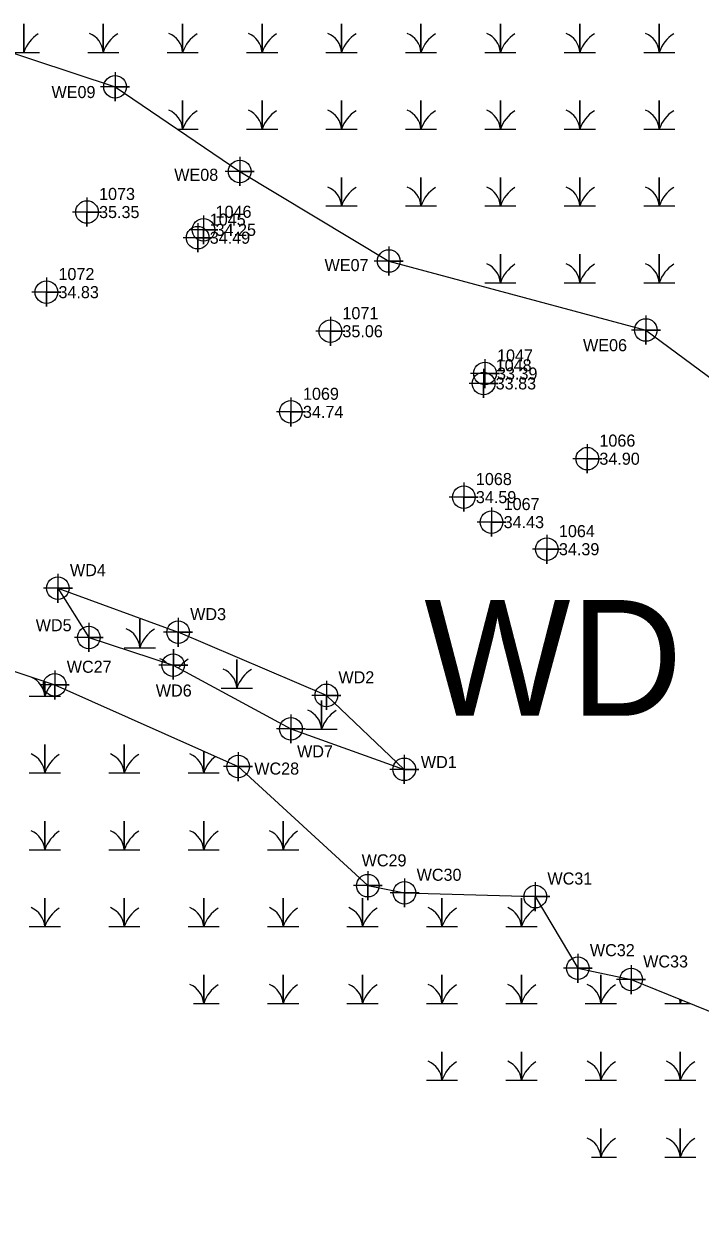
# Model space of a CAD drawing. Extents: x 2138832 to 2141061, y 149156 to 150675.
# Drawn here: x 2140647 to 2140787, y 149199.9 to 149446.4 of the extents above; entities that cross this region are included whole.
import ezdxf

# ---------------------------------------------------------------- set-up
doc = ezdxf.new("R2010")
doc.units = 0
for name, color, linetype in [('Default', 7, 'Continuous'), ('Exist Environmental Wetland Boundary', 7, 'Continuous'), ('Exist Environmental Wetland Boundary Cogo Number', 7, 'Continuous'), ('Exist Environmental Wetland Boundary Cogo Point CELL', 7, 'Continuous'), ('Exist Roads EOP Cogo Elevation', 7, 'Continuous'), ('Exist Roads EOP Cogo Number', 7, 'Continuous'), ('Exist Roads EOP Cogo Point CELL', 7, 'Continuous'), ('Exist Utilities Telephone UG FO SUE LOS C Cogo Elevation', 7, 'Continuous'), ('Exist Utilities Telephone UG FO SUE LOS C Cogo Number', 7, 'Continuous'), ('Exist Utilities Telephone UG FO SUE LOS C Cogo Point CELL', 7, 'Continuous')]:
    doc.layers.add(name, color=color, linetype=linetype)

msp = doc.modelspace()

# ---------------------------------------------------------------- linework, layer by layer
at = {"layer": 'Exist Environmental Wetland Boundary'}
for points in [[(2140626.92, 149434.6), (2140640.09, 149441.77), (2140665.85, 149433.31), (2140691.67, 149415.77), (2140722.53, 149397.21), (2140775.79, 149382.91), (2140815.44, 149353.55), (2140873.49, 149322.65), (2140932.75, 149291.76), (2140974.9, 149268.42), (2141022.6, 149236.76)], [(2140585.59, 149347.19), (2140617.17, 149321.45), (2140653.35, 149309.39)], [(2140654.01, 149329.41), (2140660.42, 149319.22), (2140677.9, 149313.49), (2140702.28, 149300.28)], [(2140654.01, 149329.41), (2140678.91, 149320.3)], [(2140725.75, 149291.89), (2140709.61, 149307.21), (2140678.91, 149320.3)], [(2140653.35, 149309.39), (2140691.33, 149292.47), (2140718.2, 149267.79)], [(2140702.28, 149300.28), (2140725.75, 149291.89)], [(2140718.2, 149267.79), (2140725.81, 149266.3), (2140752.89, 149265.52), (2140761.69, 149250.68), (2140772.72, 149248.34), (2140790.93, 149240.98), (2140838.41, 149220.19), (2140876.86, 149199.92)]]:
    msp.add_lwpolyline(points, dxfattribs=at)
at = {"layer": 'Exist Environmental Wetland Boundary Cogo Point CELL'}
for points in [[(2140644.13, 149440.44), (2140646.95, 149440.44), (2140646.95, 149446.36), (2140646.95, 149440.44), (2140650.18, 149440.44)], [(2140660.18, 149440.44), (2140663.4, 149440.44), (2140663.4, 149446.36), (2140663.4, 149440.44), (2140666.63, 149440.44)], [(2140676.63, 149440.44), (2140679.85, 149440.44), (2140679.85, 149446.36), (2140679.85, 149440.44), (2140683.08, 149440.44)], [(2140693.08, 149440.44), (2140696.3, 149440.44), (2140696.3, 149446.36), (2140696.3, 149440.44), (2140699.53, 149440.44)], [(2140709.53, 149440.44), (2140712.76, 149440.44), (2140712.76, 149446.36), (2140712.76, 149440.44), (2140715.98, 149440.44)], [(2140725.98, 149440.44), (2140729.21, 149440.44), (2140729.21, 149446.36), (2140729.21, 149440.44), (2140732.43, 149440.44)], [(2140742.43, 149440.44), (2140745.66, 149440.44), (2140745.66, 149446.36), (2140745.66, 149440.44), (2140748.88, 149440.44)], [(2140758.88, 149440.44), (2140762.11, 149440.44), (2140762.11, 149446.36), (2140762.11, 149440.44), (2140765.34, 149440.44)], [(2140775.34, 149440.44), (2140778.56, 149440.44), (2140778.56, 149446.36), (2140778.56, 149440.44), (2140781.79, 149440.44)], [(2140665.85, 149436.31), (2140665.85, 149430.31), (2140665.85, 149433.31), (2140668.85, 149433.31), (2140662.85, 149433.31)], [(2140678.79, 149424.52), (2140679.85, 149424.52), (2140679.85, 149430.44), (2140679.85, 149424.52), (2140683.08, 149424.52)], [(2140693.08, 149424.52), (2140696.3, 149424.52), (2140696.3, 149430.44), (2140696.3, 149424.52), (2140699.53, 149424.52)], [(2140709.53, 149424.52), (2140712.76, 149424.52), (2140712.76, 149430.44), (2140712.76, 149424.52), (2140715.98, 149424.52)], [(2140725.98, 149424.52), (2140729.21, 149424.52), (2140729.21, 149430.44), (2140729.21, 149424.52), (2140732.43, 149424.52)], [(2140742.43, 149424.52), (2140745.66, 149424.52), (2140745.66, 149430.44), (2140745.66, 149424.52), (2140748.88, 149424.52)], [(2140758.88, 149424.52), (2140762.11, 149424.52), (2140762.11, 149430.44), (2140762.11, 149424.52), (2140765.34, 149424.52)], [(2140775.34, 149424.52), (2140778.56, 149424.52), (2140778.56, 149430.44), (2140778.56, 149424.52), (2140781.79, 149424.52)], [(2140691.67, 149418.77), (2140691.67, 149412.77), (2140691.67, 149415.77), (2140694.67, 149415.77), (2140688.67, 149415.77)], [(2140709.53, 149408.61), (2140712.76, 149408.61), (2140712.76, 149414.52), (2140712.76, 149408.61), (2140715.98, 149408.61)], [(2140725.98, 149408.61), (2140729.21, 149408.61), (2140729.21, 149414.52), (2140729.21, 149408.61), (2140732.43, 149408.61)], [(2140742.43, 149408.61), (2140745.66, 149408.61), (2140745.66, 149414.52), (2140745.66, 149408.61), (2140748.88, 149408.61)], [(2140758.88, 149408.61), (2140762.11, 149408.61), (2140762.11, 149414.52), (2140762.11, 149408.61), (2140765.34, 149408.61)], [(2140775.34, 149408.61), (2140778.56, 149408.61), (2140778.56, 149414.52), (2140778.56, 149408.61), (2140781.79, 149408.61)], [(2140722.53, 149400.21), (2140722.53, 149394.21), (2140722.53, 149397.21), (2140725.53, 149397.21), (2140719.53, 149397.21)], [(2140742.43, 149392.69), (2140745.66, 149392.69), (2140745.66, 149398.61), (2140745.66, 149392.69), (2140748.88, 149392.69)], [(2140758.88, 149392.69), (2140762.11, 149392.69), (2140762.11, 149398.61), (2140762.11, 149392.69), (2140765.34, 149392.69)], [(2140775.34, 149392.69), (2140778.56, 149392.69), (2140778.56, 149398.61), (2140778.56, 149392.69), (2140781.79, 149392.69)], [(2140775.79, 149385.91), (2140775.79, 149379.91), (2140775.79, 149382.91), (2140778.79, 149382.91), (2140772.79, 149382.91)], [(2140654.01, 149332.41), (2140654.01, 149326.41), (2140654.01, 149329.41), (2140657.01, 149329.41), (2140651.01, 149329.41)], [(2140667.75, 149317.08), (2140670.98, 149317.08), (2140670.98, 149323), (2140670.98, 149317.08), (2140674.2, 149317.08)], [(2140678.91, 149323.3), (2140678.91, 149317.3), (2140678.91, 149320.3), (2140681.91, 149320.3), (2140675.91, 149320.3)], [(2140660.42, 149322.22), (2140660.42, 149316.22), (2140660.42, 149319.22), (2140663.42, 149319.22), (2140657.42, 149319.22)], [(2140677.9, 149316.49), (2140677.9, 149310.49), (2140677.9, 149313.49), (2140680.9, 149313.49), (2140674.9, 149313.49)], [(2140677.98, 149313.45), (2140677.98, 149316.8), (2140677.98, 149313.45)], [(2140687.86, 149308.73), (2140691.09, 149308.73), (2140691.09, 149314.64), (2140691.09, 149308.73), (2140694.32, 149308.73)], [(2140653.35, 149312.39), (2140653.35, 149306.39), (2140653.35, 149309.39), (2140656.35, 149309.39), (2140650.35, 149309.39)], [(2140648.08, 149307.06), (2140651.3, 149307.06), (2140651.3, 149310.07)], [(2140651.3, 149310.07), (2140651.3, 149307.06), (2140654.53, 149307.06)], [(2140709.61, 149310.21), (2140709.61, 149304.21), (2140709.61, 149307.21), (2140712.61, 149307.21), (2140706.61, 149307.21)], [(2140705.4, 149300.22), (2140708.63, 149300.22), (2140708.63, 149306.13), (2140708.63, 149300.22), (2140711.86, 149300.22)], [(2140702.28, 149303.28), (2140702.28, 149297.28), (2140702.28, 149300.28), (2140705.28, 149300.28), (2140699.28, 149300.28)], [(2140648.08, 149291.14), (2140651.3, 149291.14), (2140651.3, 149297.06), (2140651.3, 149291.14), (2140654.53, 149291.14)], [(2140664.53, 149291.14), (2140667.75, 149291.14), (2140667.75, 149297.06), (2140667.75, 149291.14), (2140670.98, 149291.14)], [(2140680.98, 149291.14), (2140684.21, 149291.14), (2140684.21, 149295.64)], [(2140684.21, 149295.64), (2140684.21, 149291.14), (2140687.43, 149291.14)], [(2140691.33, 149295.47), (2140691.33, 149289.47), (2140691.33, 149292.47), (2140694.33, 149292.47), (2140688.33, 149292.47)], [(2140725.75, 149294.89), (2140725.75, 149288.89), (2140725.75, 149291.89), (2140728.75, 149291.89), (2140722.75, 149291.89)], [(2140648.08, 149275.22), (2140651.3, 149275.22), (2140651.3, 149281.14), (2140651.3, 149275.22), (2140654.53, 149275.22)], [(2140664.53, 149275.22), (2140667.75, 149275.22), (2140667.75, 149281.14), (2140667.75, 149275.22), (2140670.98, 149275.22)], [(2140680.98, 149275.22), (2140684.21, 149275.22), (2140684.21, 149281.14), (2140684.21, 149275.22), (2140687.43, 149275.22)], [(2140697.43, 149275.22), (2140700.66, 149275.22), (2140700.66, 149281.14), (2140700.66, 149275.22), (2140703.88, 149275.22)], [(2140718.2, 149270.79), (2140718.2, 149264.79), (2140718.2, 149267.79), (2140721.2, 149267.79), (2140715.2, 149267.79)], [(2140725.81, 149269.3), (2140725.81, 149263.3), (2140725.81, 149266.3), (2140728.81, 149266.3), (2140722.81, 149266.3)], [(2140752.89, 149268.52), (2140752.89, 149262.52), (2140752.89, 149265.52), (2140755.89, 149265.52), (2140749.89, 149265.52)], [(2140648.08, 149259.31), (2140651.3, 149259.31), (2140651.3, 149265.22), (2140651.3, 149259.31), (2140654.53, 149259.31)], [(2140664.53, 149259.31), (2140667.75, 149259.31), (2140667.75, 149265.22), (2140667.75, 149259.31), (2140670.98, 149259.31)], [(2140680.98, 149259.31), (2140684.21, 149259.31), (2140684.21, 149265.22), (2140684.21, 149259.31), (2140687.43, 149259.31)], [(2140697.43, 149259.31), (2140700.66, 149259.31), (2140700.66, 149265.22), (2140700.66, 149259.31), (2140703.88, 149259.31)], [(2140713.88, 149259.31), (2140717.11, 149259.31), (2140717.11, 149265.22), (2140717.11, 149259.31), (2140720.33, 149259.31)], [(2140730.33, 149259.31), (2140733.56, 149259.31), (2140733.56, 149265.22), (2140733.56, 149259.31), (2140736.79, 149259.31)], [(2140746.79, 149259.31), (2140750.01, 149259.31), (2140750.01, 149265.22), (2140750.01, 149259.31), (2140753.24, 149259.31)], [(2140761.69, 149253.68), (2140761.69, 149247.68), (2140761.69, 149250.68), (2140764.69, 149250.68), (2140758.69, 149250.68)], [(2140772.72, 149251.34), (2140772.72, 149245.34), (2140772.72, 149248.34), (2140775.72, 149248.34), (2140769.72, 149248.34)], [(2140682.1, 149243.39), (2140684.21, 149243.39), (2140684.21, 149249.31), (2140684.21, 149243.39), (2140687.43, 149243.39)], [(2140697.43, 149243.39), (2140700.66, 149243.39), (2140700.66, 149249.31), (2140700.66, 149243.39), (2140703.88, 149243.39)], [(2140713.88, 149243.39), (2140717.11, 149243.39), (2140717.11, 149249.31), (2140717.11, 149243.39), (2140720.33, 149243.39)], [(2140730.33, 149243.39), (2140733.56, 149243.39), (2140733.56, 149249.31), (2140733.56, 149243.39), (2140736.79, 149243.39)], [(2140746.79, 149243.39), (2140750.01, 149243.39), (2140750.01, 149249.31), (2140750.01, 149243.39), (2140753.24, 149243.39)], [(2140763.24, 149243.39), (2140766.46, 149243.39), (2140766.46, 149249.31), (2140766.46, 149243.39), (2140769.69, 149243.39)], [(2140779.69, 149243.39), (2140782.91, 149243.39), (2140782.91, 149244.22)], [(2140782.91, 149244.22), (2140782.91, 149243.39), (2140784.98, 149243.39)], [(2140730.33, 149227.47), (2140733.56, 149227.47), (2140733.56, 149233.39), (2140733.56, 149227.47), (2140736.79, 149227.47)], [(2140746.79, 149227.47), (2140750.01, 149227.47), (2140750.01, 149233.39), (2140750.01, 149227.47), (2140753.24, 149227.47)], [(2140763.24, 149227.47), (2140766.46, 149227.47), (2140766.46, 149233.39), (2140766.46, 149227.47), (2140769.69, 149227.47)], [(2140779.69, 149227.47), (2140782.91, 149227.47), (2140782.91, 149233.39), (2140782.91, 149227.47), (2140786.14, 149227.47)], [(2140764.54, 149211.55), (2140766.46, 149211.55), (2140766.46, 149217.47), (2140766.46, 149211.55), (2140769.69, 149211.55)], [(2140779.69, 149211.55), (2140782.91, 149211.55), (2140782.91, 149217.47), (2140782.91, 149211.55), (2140786.14, 149211.55)]]:
    msp.add_lwpolyline(points, dxfattribs=at)
for centre in [(2140665.85, 149433.31), (2140691.67, 149415.77), (2140722.53, 149397.21), (2140775.79, 149382.91), (2140654.01, 149329.41), (2140678.91, 149320.3), (2140660.42, 149319.22), (2140677.9, 149313.49), (2140653.35, 149309.39), (2140709.61, 149307.21), (2140702.28, 149300.28), (2140691.33, 149292.47), (2140725.75, 149291.89), (2140718.2, 149267.79), (2140725.81, 149266.3), (2140752.89, 149265.52), (2140761.69, 149250.68), (2140772.72, 149248.34)]:
    msp.add_circle(centre, 2.34, dxfattribs=at)
for centre, radius, start, end in [((2140653.79, 149438.17), 7.21, 122.1274, 161.6222), ((2140658.8, 149440.11), 4.61, 4.1403, 67.535), ((2140670.24, 149438.17), 7.21, 122.1274, 161.6222), ((2140675.25, 149440.11), 4.61, 4.1403, 67.535), ((2140686.69, 149438.17), 7.21, 122.1274, 161.6222), ((2140691.7, 149440.11), 4.61, 4.1403, 67.535), ((2140703.15, 149438.17), 7.21, 122.1274, 161.6222), ((2140708.16, 149440.11), 4.61, 4.1403, 67.535), ((2140719.6, 149438.17), 7.21, 122.1274, 161.6222), ((2140724.61, 149440.11), 4.61, 4.1403, 67.535), ((2140736.05, 149438.17), 7.21, 122.1274, 161.6222), ((2140741.06, 149440.11), 4.61, 4.1403, 67.535), ((2140752.5, 149438.17), 7.21, 122.1274, 161.6222), ((2140757.51, 149440.11), 4.61, 4.1403, 67.535), ((2140768.95, 149438.17), 7.21, 122.1274, 161.6222), ((2140773.96, 149440.11), 4.61, 4.1403, 67.535), ((2140785.4, 149438.17), 7.21, 122.1274, 161.6222), ((2140675.25, 149424.19), 4.61, 4.1403, 67.535), ((2140686.69, 149422.25), 7.21, 122.1274, 161.6222), ((2140691.7, 149424.19), 4.61, 4.1403, 67.535), ((2140703.15, 149422.25), 7.21, 122.1274, 161.6222), ((2140708.16, 149424.19), 4.61, 4.1403, 67.535), ((2140719.6, 149422.25), 7.21, 122.1274, 161.6222), ((2140724.61, 149424.19), 4.61, 4.1403, 67.535), ((2140736.05, 149422.25), 7.21, 122.1274, 161.6222), ((2140741.06, 149424.19), 4.61, 4.1403, 67.535), ((2140752.5, 149422.25), 7.21, 122.1274, 161.6222), ((2140757.51, 149424.19), 4.61, 4.1403, 67.535), ((2140768.95, 149422.25), 7.21, 122.1274, 161.6222), ((2140773.96, 149424.19), 4.61, 4.1403, 67.535), ((2140785.4, 149422.25), 7.21, 122.1274, 161.6222), ((2140708.16, 149408.27), 4.61, 4.1403, 67.535), ((2140719.6, 149406.33), 7.21, 122.1274, 161.6222), ((2140724.61, 149408.27), 4.61, 4.1403, 67.535), ((2140736.05, 149406.33), 7.21, 122.1274, 161.6222), ((2140741.06, 149408.27), 4.61, 4.1403, 67.535), ((2140752.5, 149406.33), 7.21, 122.1274, 161.6222), ((2140757.51, 149408.27), 4.61, 4.1403, 67.535), ((2140768.95, 149406.33), 7.21, 122.1274, 161.6222), ((2140773.96, 149408.27), 4.61, 4.1403, 67.535), ((2140785.4, 149406.33), 7.21, 122.1274, 161.6222), ((2140741.06, 149392.36), 4.61, 4.1403, 67.535), ((2140757.51, 149392.36), 4.61, 4.1403, 67.535), ((2140773.96, 149392.36), 4.61, 4.1403, 67.535), ((2140752.5, 149390.42), 7.21, 122.1274, 161.6222), ((2140768.95, 149390.42), 7.21, 122.1274, 161.6222), ((2140785.4, 149390.42), 7.21, 122.1274, 161.6222), ((2140666.38, 149316.75), 4.61, 4.1403, 67.535), ((2140677.82, 149314.81), 7.21, 122.1274, 161.6222), ((2140673.38, 149310.55), 4.61, 47.5643, 67.535), ((2140684.82, 149308.61), 7.21, 122.1274, 143.5992), ((2140646.7, 149306.73), 4.61, 4.1403, 67.535), ((2140686.49, 149308.39), 4.61, 4.1403, 67.535), ((2140697.93, 149306.45), 7.21, 122.1274, 161.6222), ((2140658.14, 149304.79), 7.21, 138.3045, 161.6222), ((2140704.03, 149299.88), 4.61, 4.1403, 67.535), ((2140715.47, 149297.94), 7.21, 122.1274, 161.6222), ((2140646.7, 149290.81), 4.61, 4.1403, 67.535), ((2140658.14, 149288.87), 7.21, 122.1274, 161.6222), ((2140663.15, 149290.81), 4.61, 4.1403, 67.535), ((2140674.6, 149288.87), 7.21, 122.1274, 161.6222), ((2140679.61, 149290.81), 4.61, 4.1403, 67.535), ((2140691.05, 149288.87), 7.21, 127.7972, 161.6222), ((2140646.7, 149274.89), 4.61, 4.1403, 67.535), ((2140658.14, 149272.95), 7.21, 122.1274, 161.6222), ((2140663.15, 149274.89), 4.61, 4.1403, 67.535), ((2140674.6, 149272.95), 7.21, 122.1274, 161.6222), ((2140679.61, 149274.89), 4.61, 4.1403, 67.535), ((2140691.05, 149272.95), 7.21, 122.1274, 161.6222), ((2140696.06, 149274.89), 4.61, 4.1403, 67.535), ((2140707.5, 149272.95), 7.21, 122.1274, 161.6222), ((2140646.7, 149258.97), 4.61, 4.1403, 67.535), ((2140658.14, 149257.03), 7.21, 122.1274, 161.6222), ((2140663.15, 149258.97), 4.61, 4.1403, 67.535), ((2140674.6, 149257.03), 7.21, 122.1274, 161.6222), ((2140679.61, 149258.97), 4.61, 4.1403, 67.535), ((2140691.05, 149257.03), 7.21, 122.1274, 161.6222), ((2140696.06, 149258.97), 4.61, 4.1403, 67.535), ((2140707.5, 149257.03), 7.21, 122.1274, 161.6222), ((2140712.51, 149258.97), 4.61, 4.1403, 67.535), ((2140723.95, 149257.03), 7.21, 122.1274, 161.6222), ((2140728.96, 149258.97), 4.61, 4.1403, 67.535), ((2140740.4, 149257.03), 7.21, 122.1274, 161.6222), ((2140745.41, 149258.97), 4.61, 4.1403, 67.535), ((2140756.85, 149257.03), 7.21, 122.1274, 161.6222), ((2140679.61, 149243.05), 4.61, 4.1403, 67.535), ((2140691.05, 149241.12), 7.21, 122.1274, 161.6222), ((2140696.06, 149243.05), 4.61, 4.1403, 67.535), ((2140707.5, 149241.12), 7.21, 122.1274, 161.6222), ((2140712.51, 149243.05), 4.61, 4.1403, 67.535), ((2140723.95, 149241.12), 7.21, 122.1274, 161.6222), ((2140728.96, 149243.05), 4.61, 4.1403, 67.535), ((2140740.4, 149241.12), 7.21, 122.1274, 161.6222), ((2140745.41, 149243.05), 4.61, 4.1403, 67.535), ((2140756.85, 149241.12), 7.21, 122.1274, 161.6222), ((2140761.86, 149243.05), 4.61, 4.1403, 67.535), ((2140773.3, 149241.12), 7.21, 122.1274, 161.6222), ((2140778.31, 149243.05), 4.61, 4.1403, 15.4513), ((2140789.75, 149241.12), 7.21, 155.4777, 161.6222), ((2140728.96, 149227.14), 4.61, 4.1403, 67.535), ((2140740.4, 149225.2), 7.21, 122.1274, 161.6222), ((2140745.41, 149227.14), 4.61, 4.1403, 67.535), ((2140756.85, 149225.2), 7.21, 122.1274, 161.6222), ((2140761.86, 149227.14), 4.61, 4.1403, 67.535), ((2140773.3, 149225.2), 7.21, 122.1274, 161.6222), ((2140778.31, 149227.14), 4.61, 4.1403, 67.535), ((2140789.75, 149225.2), 7.21, 122.1274, 161.6222), ((2140761.86, 149211.22), 4.61, 4.1403, 67.535), ((2140773.3, 149209.28), 7.21, 122.1274, 161.6222), ((2140778.31, 149211.22), 4.61, 4.1403, 67.535), ((2140789.75, 149209.28), 7.21, 122.1274, 161.6222)]:
    msp.add_arc(centre, radius, start, end, dxfattribs=at)
at = {"layer": 'Exist Roads EOP Cogo Point CELL'}
for points in [[(2140660.04, 149410.36), (2140660.04, 149404.36), (2140660.04, 149407.36), (2140663.04, 149407.36), (2140657.04, 149407.36)], [(2140651.63, 149393.76), (2140651.63, 149387.76), (2140651.63, 149390.76), (2140654.63, 149390.76), (2140648.63, 149390.76)], [(2140710.44, 149385.66), (2140710.44, 149379.66), (2140710.44, 149382.66), (2140713.44, 149382.66), (2140707.44, 149382.66)], [(2140702.27, 149368.95), (2140702.27, 149362.95), (2140702.27, 149365.95), (2140705.27, 149365.95), (2140699.27, 149365.95)], [(2140763.66, 149359.25), (2140763.66, 149353.25), (2140763.66, 149356.25), (2140766.66, 149356.25), (2140760.66, 149356.25)], [(2140738.08, 149351.29), (2140738.08, 149345.29), (2140738.08, 149348.29), (2140741.08, 149348.29), (2140735.08, 149348.29)], [(2140743.83, 149346.11), (2140743.83, 149340.11), (2140743.83, 149343.11), (2140746.83, 149343.11), (2140740.83, 149343.11)], [(2140755.28, 149340.5), (2140755.28, 149334.5), (2140755.28, 149337.5), (2140758.28, 149337.5), (2140752.28, 149337.5)]]:
    msp.add_lwpolyline(points, dxfattribs=at)
for centre in [(2140660.04, 149407.36), (2140651.63, 149390.76), (2140710.44, 149382.66), (2140702.27, 149365.95), (2140763.66, 149356.25), (2140738.08, 149348.29), (2140743.83, 149343.11), (2140755.28, 149337.5)]:
    msp.add_circle(centre, 2.34, dxfattribs=at)
at = {"layer": 'Exist Utilities Telephone UG FO SUE LOS C Cogo Point CELL'}
for points in [[(2140684.17, 149406.67), (2140684.17, 149400.67), (2140684.17, 149403.67), (2140687.17, 149403.67), (2140681.17, 149403.67)], [(2140682.96, 149405.04), (2140682.96, 149399.04), (2140682.96, 149402.04), (2140685.96, 149402.04), (2140679.96, 149402.04)], [(2140742.46, 149376.89), (2140742.46, 149370.89), (2140742.46, 149373.89), (2140745.46, 149373.89), (2140739.46, 149373.89)], [(2140742.18, 149374.85), (2140742.18, 149368.85), (2140742.18, 149371.85), (2140745.18, 149371.85), (2140739.18, 149371.85)]]:
    msp.add_lwpolyline(points, dxfattribs=at)
for centre in [(2140682.96, 149402.04), (2140684.17, 149403.67), (2140742.46, 149373.89), (2140742.18, 149371.85)]:
    msp.add_circle(centre, 2.34, dxfattribs=at)

# ---------------------------------------------------------------- texts
at = {"layer": 'Default'}
msp.add_text('WD', height=24, dxfattribs=at).set_placement((2140729.88, 149302.98))
at = {"layer": 'Exist Environmental Wetland Boundary Cogo Number'}
for s, p in [('WE09', (2140652.69, 149430.97)), ('WE08', (2140678.11, 149413.82)), ('WE07', (2140709.24, 149395.12)), ('WE06', (2140762.77, 149378.52)), ('WD4', (2140656.51, 149331.91)), ('WD3', (2140681.41, 149322.8)), ('WD5', (2140649.42, 149320.5)), ('WC27', (2140655.85, 149311.89)), ('WD2', (2140712.11, 149309.71)), ('WD6', (2140674.29, 149306.97)), ('WD7', (2140703.55, 149294.36)), ('WC28', (2140694.68, 149290.8)), ('WD1', (2140729.18, 149292.15)), ('WC29', (2140716.92, 149271.78)), ('WC30', (2140728.31, 149268.8)), ('WC31', (2140755.39, 149268.02)), ('WC32', (2140764.19, 149253.18)), ('WC33', (2140775.22, 149250.84))]:
    msp.add_text(s, height=2.5, dxfattribs=at).set_placement(p)
at = {"layer": 'Exist Roads EOP Cogo Elevation'}
for s, p in [('35.35', (2140662.54, 149406.11)), ('34.83', (2140654.13, 149389.51)), ('35.06', (2140712.94, 149381.41)), ('34.74', (2140704.77, 149364.7)), ('34.90', (2140766.16, 149355)), ('34.59', (2140740.58, 149347.04)), ('34.43', (2140746.33, 149341.86)), ('34.39', (2140757.78, 149336.25))]:
    msp.add_text(s, height=2.5, dxfattribs=at).set_placement(p)
at = {"layer": 'Exist Roads EOP Cogo Number'}
for s, p in [('1073', (2140662.54, 149409.86)), ('1072', (2140654.13, 149393.26)), ('1071', (2140712.94, 149385.16)), ('1069', (2140704.77, 149368.45)), ('1066', (2140766.16, 149358.75)), ('1068', (2140740.58, 149350.79)), ('1067', (2140746.33, 149345.61)), ('1064', (2140757.78, 149340))]:
    msp.add_text(s, height=2.5, dxfattribs=at).set_placement(p)
at = {"layer": 'Exist Utilities Telephone UG FO SUE LOS C Cogo Elevation'}
for s, p in [('34.25', (2140686.67, 149402.42)), ('34.49', (2140685.46, 149400.79)), ('33.39', (2140744.96, 149372.64)), ('33.83', (2140744.68, 149370.6))]:
    msp.add_text(s, height=2.5, dxfattribs=at).set_placement(p)
at = {"layer": 'Exist Utilities Telephone UG FO SUE LOS C Cogo Number'}
for s, p in [('1045', (2140685.46, 149404.54)), ('1046', (2140686.67, 149406.17)), ('1048', (2140744.68, 149374.35)), ('1047', (2140744.96, 149376.39))]:
    msp.add_text(s, height=2.5, dxfattribs=at).set_placement(p)

doc.saveas('drawing.dxf')
